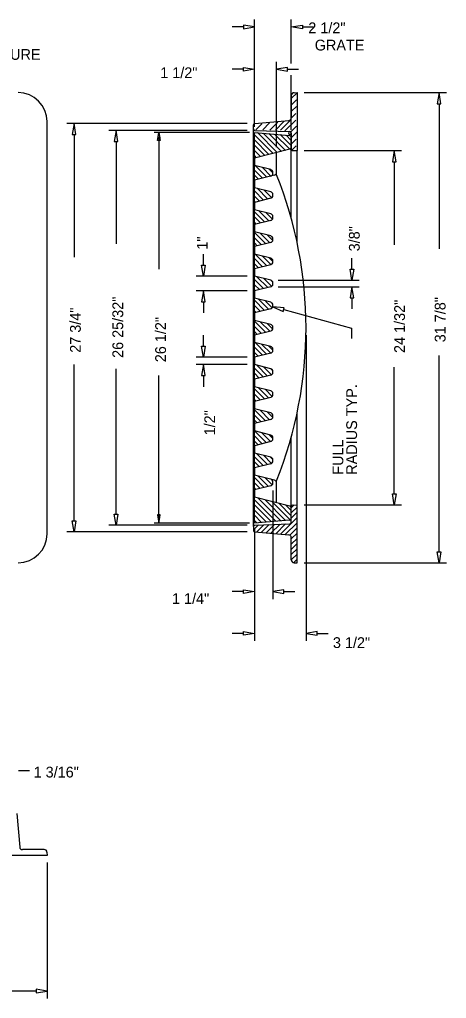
# Model space of a CAD drawing. Extents: x 12.38 to 19.62, y 5.98 to 15.83.
# Drawn here: x 17.01 to 19.38, y 10.38 to 15.83 of the extents above; entities that cross this region are included whole.
import ezdxf

# ---------------------------------------------------------------- set-up
doc = ezdxf.new("R2010")
doc.units = 0
for name, color, linetype in [('Default', 7, 'Continuous'), ('DIMS', 7, 'Continuous'), ('FRAME', 7, 'Continuous'), ('HATCH', 7, 'Continuous'), ('TOP', 7, 'Continuous'), ('V7_LEVEL_12', 7, 'Continuous')]:
    doc.layers.add(name, color=color, linetype=linetype)

# ---------------------------------------------------------------- blocks, each defined once
blk = doc.blocks.new('_X18')
at = {"layer": 'Default'}
for p, q in [((224.48, 235.08), (225.53, 236.13)), ((225.18, 232.25), (229.06, 236.13)), ((225.89, 229.43), (232.6, 236.13)), ((226.6, 226.6), (233.57, 233.57)), ((227.6, 224.07), (232.4, 228.86))]:
    blk.add_line(p, q, dxfattribs=at)
blk = doc.blocks.new('_X19')
at = {"layer": 'Default'}
for p, q in [((239.3, 235.77), (239.67, 236.13)), ((240.01, 232.94), (243.2, 236.13)), ((240.72, 230.11), (246.74, 236.13)), ((241.43, 227.28), (248.86, 234.72)), ((242.2, 224.53), (247.68, 230)), ((244.86, 223.65), (246.5, 225.29))]:
    blk.add_line(p, q, dxfattribs=at)
blk = doc.blocks.new('_X20')
at = {"layer": 'Default'}
for p, q in [((254.84, 233.63), (257.35, 236.13)), ((255.55, 230.8), (260.88, 236.13)), ((256.25, 227.97), (264.15, 235.86)), ((256.96, 225.14), (262.97, 231.15)), ((258.99, 223.63), (261.79, 226.43))]:
    blk.add_line(p, q, dxfattribs=at)
blk = doc.blocks.new('_X21')
at = {"layer": 'Default'}
for p, q in [((269.67, 234.31), (271.49, 236.13)), ((270.38, 231.48), (275.02, 236.13)), ((271.08, 228.66), (278.56, 236.13)), ((271.79, 225.83), (278.25, 232.29)), ((273.22, 223.72), (277.07, 227.58))]:
    blk.add_line(p, q, dxfattribs=at)
blk = doc.blocks.new('_X22')
at = {"layer": 'Default'}
for p, q in [((284.5, 235), (285.63, 236.13)), ((285.2, 232.17), (289.16, 236.13)), ((285.91, 229.34), (292.7, 236.13)), ((286.62, 226.51), (293.54, 233.43)), ((287.66, 224.02), (292.36, 228.72))]:
    blk.add_line(p, q, dxfattribs=at)
blk = doc.blocks.new('_X23')
at = {"layer": 'Default'}
for p, q in [((299.32, 235.69), (299.77, 236.13)), ((300.03, 232.86), (303.31, 236.13)), ((300.74, 230.03), (306.84, 236.13)), ((301.45, 227.2), (308.82, 234.58)), ((302.24, 224.46), (307.65, 229.86)), ((304.98, 223.67), (306.47, 225.15))]:
    blk.add_line(p, q, dxfattribs=at)
blk = doc.blocks.new('_X24')
at = {"layer": 'Default'}
for p, q in [((314.86, 233.54), (317.45, 236.13)), ((315.57, 230.71), (320.98, 236.13)), ((316.27, 227.89), (324.11, 235.72)), ((316.98, 225.06), (322.93, 231.01)), ((319.09, 223.63), (321.75, 226.29))]:
    blk.add_line(p, q, dxfattribs=at)
blk = doc.blocks.new('_X25')
at = {"layer": 'Default'}
for p, q in [((329.69, 234.23), (331.59, 236.13)), ((330.4, 231.4), (335.13, 236.13)), ((331.1, 228.57), (338.66, 236.13)), ((331.81, 225.74), (338.22, 232.15)), ((333.3, 223.7), (337.04, 227.44))]:
    blk.add_line(p, q, dxfattribs=at)
blk = doc.blocks.new('_X26')
at = {"layer": 'Default'}
for p, q in [((344.52, 234.92), (345.73, 236.13)), ((345.22, 232.09), (349.27, 236.13)), ((345.93, 229.26), (352.8, 236.13)), ((346.64, 226.43), (353.5, 233.3)), ((347.72, 223.98), (352.33, 228.58))]:
    blk.add_line(p, q, dxfattribs=at)
blk = doc.blocks.new('_X27')
at = {"layer": 'Default'}
for p, q in [((359.35, 235.6), (359.88, 236.13)), ((360.05, 232.77), (363.41, 236.13)), ((360.76, 229.95), (366.95, 236.13)), ((361.47, 227.12), (368.79, 234.44)), ((362.29, 224.4), (367.61, 229.73)), ((365.12, 223.7), (366.43, 225.01))]:
    blk.add_line(p, q, dxfattribs=at)
blk = doc.blocks.new('_X28')
at = {"layer": 'Default'}
for p, q in [((374.88, 233.46), (377.55, 236.13)), ((375.59, 230.63), (381.09, 236.13)), ((376.3, 227.8), (384.08, 235.58)), ((377, 224.98), (382.9, 230.87)), ((379.2, 223.63), (381.72, 226.16))]:
    blk.add_line(p, q, dxfattribs=at)
blk = doc.blocks.new('_X29')
at = {"layer": 'Default'}
for p, q in [((389.71, 234.15), (391.7, 236.13)), ((390.42, 231.32), (395.23, 236.13)), ((391.12, 228.49), (398.77, 236.13)), ((391.83, 225.66), (398.18, 232.01)), ((393.38, 223.68), (397.01, 227.3))]:
    blk.add_line(p, q, dxfattribs=at)
blk = doc.blocks.new('_X30')
at = {"layer": 'Default'}
for p, q in [((404.54, 234.83), (405.84, 236.13)), ((405.25, 232), (409.37, 236.13)), ((405.95, 229.18), (412.91, 236.13)), ((406.66, 226.35), (413.47, 233.16)), ((407.78, 223.93), (412.29, 228.44))]:
    blk.add_line(p, q, dxfattribs=at)
blk = doc.blocks.new('_X31')
at = {"layer": 'Default'}
for p, q in [((419.37, 235.52), (419.98, 236.13)), ((420.07, 232.69), (423.52, 236.13)), ((420.78, 229.86), (427.05, 236.13)), ((421.49, 227.03), (428.76, 234.3)), ((422.33, 224.34), (427.58, 229.59)), ((425.27, 223.75), (426.38, 224.86))]:
    blk.add_line(p, q, dxfattribs=at)
blk = doc.blocks.new('_X32')
at = {"layer": 'Default'}
for p, q in [((434.9, 233.38), (437.66, 236.13)), ((435.61, 230.55), (441.19, 236.13)), ((436.32, 227.72), (444.04, 235.45)), ((437.03, 224.9), (442.86, 230.73)), ((439.3, 223.63), (441.68, 226.02))]:
    blk.add_line(p, q, dxfattribs=at)
blk = doc.blocks.new('_X38')
at = {"layer": 'Default'}
for p, q in [((865.44, 393.21), (850.84, 407.81)), ((868.69, 393.49), (853.39, 408.8)), ((871.94, 393.78), (858.1, 407.62)), ((875.12, 394.13), (862.82, 406.44)), ((875.84, 396.95), (867.53, 405.26)), ((862.19, 392.92), (850.84, 404.27)), ((858.94, 392.64), (850.84, 400.73)), ((875.84, 400.48), (872.25, 404.08)), ((855.69, 392.36), (850.84, 397.2)), ((852.44, 392.07), (850.84, 393.66))]:
    blk.add_line(p, q, dxfattribs=at)
blk = doc.blocks.new('_X49')
at = {"layer": 'Default'}
for p, q in [((772.6, 411.98), (774.45, 413.83)), ((772.6, 408.44), (776.54, 412.38)), ((765.29, 394.06), (776.54, 405.31)), ((772.6, 404.9), (776.54, 408.84)), ((747.01, 396.99), (750.31, 400.29)), ((749.03, 395.48), (753.97, 400.42)), ((752.29, 395.2), (757.64, 400.55)), ((755.54, 394.91), (761.3, 400.68)), ((758.79, 394.63), (764.96, 400.8)), ((762.04, 394.34), (768.63, 400.93)), ((768.54, 393.77), (776.54, 401.77)), ((771.64, 393.34), (776.54, 398.24)), ((772.6, 390.76), (776.54, 394.7)), ((772.6, 387.23), (776.54, 391.17)), ((772.6, 383.69), (776.54, 387.63)), ((772.6, 380.16), (776.54, 384.1)), ((772.6, 376.62), (776.54, 380.56)), ((774.23, 374.72), (776.54, 377.02))]:
    blk.add_line(p, q, dxfattribs=at)

msp = doc.modelspace()

# ---------------------------------------------------------------- linework, layer by layer
at = {"layer": 'DIMS'}
for p, q in [((18.3147, 15.2408), (18.3147, 15.8273)), ((18.5197, 15.5828), (18.5197, 15.8273)), ((18.2531, 15.7863), (18.1916, 15.7863)), ((18.5812, 15.7863), (18.6427, 15.7863)), ((18.3147, 15.2302), (18.3147, 15.5924)), ((18.4377, 15.1182), (18.4377, 15.5924)), ((18.2531, 15.5514), (18.1916, 15.5514)), ((18.4992, 15.5514), (18.5607, 15.5514)), ((18.5197, 15.2135), (18.5197, 15.5175)), ((18.5918, 15.4209), (19.3826, 15.4209)), ((19.3415, 15.3594), (19.3415, 14.5513)), ((18.2737, 15.2487), (17.2709, 15.2487)), ((18.2737, 15.211), (17.5046, 15.211)), ((18.2873, 15.1998), (17.7564, 15.1998)), ((18.2873, 15.1998), (17.7564, 15.1998)), ((17.3119, 15.1871), (17.3119, 14.5057)), ((17.5456, 15.1495), (17.5456, 14.5793)), ((17.7837, 15.1691), (17.7837, 15.1178)), ((17.7837, 15.1691), (17.7837, 14.4395)), ((18.5918, 15.0981), (19.1336, 15.0981)), ((19.0926, 15.0366), (19.0926, 14.5746)), ((18.0313, 14.4616), (18.0313, 14.5231)), ((18.8568, 14.4389), (18.8568, 14.5004)), ((18.2736, 14.4001), (17.9903, 14.4001)), ((18.4465, 14.3774), (18.8978, 14.3774)), ((18.4465, 14.3408), (18.8978, 14.3408)), ((18.2736, 14.3181), (17.9903, 14.3181)), ((18.8568, 14.2793), (18.8568, 14.2178)), ((18.0313, 14.2566), (18.0313, 14.1951)), ((18.4774, 14.2138), (18.8553, 14.1108)), ((18.8553, 14.1108), (18.8553, 14.054)), ((18.0313, 14.0105), (18.0313, 14.072)), ((18.6017, 14.072), (18.6017, 12.3719)), ((18.2736, 13.949), (17.9903, 13.949)), ((19.3415, 12.8667), (19.3415, 13.9585)), ((17.3119, 13.0396), (17.3119, 13.9082)), ((18.2736, 13.908), (17.9903, 13.908)), ((19.0926, 13.1895), (19.0926, 13.893)), ((17.5456, 13.0766), (17.5456, 13.8853)), ((17.7837, 13.057), (17.7837, 13.8471)), ((18.0313, 13.8465), (18.0313, 13.785)), ((18.4172, 13.2074), (18.4172, 12.6039)), ((18.5918, 13.128), (19.1336, 13.128)), ((17.7837, 13.057), (17.7837, 13.0878)), ((18.2737, 13.0151), (17.5046, 13.0151)), ((18.2873, 13.0263), (17.7564, 13.0263)), ((18.2737, 12.9781), (17.2709, 12.9781)), ((18.3147, 12.9935), (18.3147, 12.3719)), ((18.5918, 12.8052), (19.3826, 12.8052)), ((18.2531, 12.6449), (18.1916, 12.6449)), ((18.4787, 12.6449), (18.5402, 12.6449)), ((18.2531, 12.4129), (18.1916, 12.4129)), ((18.6632, 12.4129), (18.7248, 12.4129)), ((17.0017, 11.6493), (17.0632, 11.6493)), ((17.1617, 11.1383), (17.1617, 10.3821)), ((17.1002, 10.4231), (15.3179, 10.4245))]:
    msp.add_line(p, q, dxfattribs=at)
for points in [[(18.2531, 15.7965), (18.2531, 15.776), (18.3147, 15.7863)], [(18.5812, 15.7965), (18.5812, 15.776), (18.5197, 15.7863)], [(18.2531, 15.5411), (18.2531, 15.5616), (18.3147, 15.5514)], [(18.4992, 15.5411), (18.4992, 15.5616), (18.4377, 15.5514)], [(19.3313, 15.3594), (19.3518, 15.3594), (19.3415, 15.4209)], [(17.3017, 15.1871), (17.3222, 15.1871), (17.3119, 15.2487)], [(17.5353, 15.1495), (17.5558, 15.1495), (17.5456, 15.211)], [(17.7913, 15.1537), (17.7759, 15.1537), (17.7836, 15.1998)], [(17.7889, 15.1691), (17.7786, 15.1691), (17.7837, 15.1998)], [(19.0824, 15.0366), (19.1029, 15.0366), (19.0926, 15.0981)], [(18.0211, 14.4616), (18.0416, 14.4616), (18.0313, 14.4001)], [(18.8466, 14.4389), (18.8671, 14.4389), (18.8568, 14.3774)], [(18.8466, 14.2793), (18.8671, 14.2793), (18.8568, 14.3408)], [(18.0211, 14.2566), (18.0416, 14.2566), (18.0313, 14.3181)], [(18.4747, 14.2039), (18.4801, 14.2237), (18.418, 14.23)], [(18.0211, 14.0105), (18.0416, 14.0105), (18.0313, 13.949)], [(18.0211, 13.8465), (18.0416, 13.8465), (18.0313, 13.908)], [(19.0824, 13.1895), (19.1029, 13.1895), (19.0926, 13.128)], [(17.5353, 13.0766), (17.5558, 13.0766), (17.5456, 13.0151)], [(17.7914, 13.0724), (17.776, 13.0724), (17.7837, 13.0263)], [(17.3017, 13.0396), (17.3222, 13.0396), (17.3119, 12.9781)], [(17.7889, 13.057), (17.7786, 13.057), (17.7837, 13.0263)], [(19.3313, 12.8667), (19.3518, 12.8667), (19.3415, 12.8052)], [(18.2531, 12.6346), (18.2531, 12.6552), (18.3147, 12.6449)], [(18.4787, 12.6346), (18.4787, 12.6552), (18.4172, 12.6449)], [(18.2531, 12.4026), (18.2531, 12.4231), (18.3147, 12.4129)], [(18.6632, 12.4026), (18.6632, 12.4231), (18.6017, 12.4129)], [(17.1002, 10.4333), (17.1002, 10.4128), (17.1617, 10.4231)]]:
    msp.add_lwpolyline(points, close=True, dxfattribs=at)
at = {"layer": 'FRAME'}
for p, q in [((18.535, 15.4203), (18.552, 15.4212)), ((18.552, 15.4212), (18.552, 15.0984)), ((18.5197, 15.4045), (18.5197, 15.2811)), ((17.1617, 12.9667), (17.1617, 15.2594)), ((18.3168, 15.2493), (18.5057, 15.2658)), ((18.3098, 15.2187), (18.3098, 15.2413)), ((18.3098, 13.0074), (18.3098, 15.2174)), ((18.3172, 15.211), (18.5123, 15.2042)), ((18.5197, 15.1965), (18.5197, 15.1063)), ((18.5197, 14.7205), (18.5197, 15.1063)), ((18.5259, 15.0998), (18.552, 15.0984)), ((18.552, 14.5877), (18.552, 15.0984)), ((18.552, 13.1276), (18.552, 13.6384)), ((18.5197, 13.1198), (18.5197, 13.5055)), ((18.5259, 13.1263), (18.552, 13.1276)), ((18.552, 12.8049), (18.552, 13.1276)), ((18.5197, 13.0296), (18.5197, 13.1198)), ((18.3172, 13.0151), (18.5123, 13.0219)), ((18.3098, 13.0077), (18.3098, 12.9851)), ((18.3098, 13.0074), (18.3098, 12.9848)), ((18.3168, 12.9774), (18.5057, 12.9609)), ((18.5197, 12.8218), (18.5197, 12.9456)), ((18.5343, 12.8065), (18.552, 12.8055)), ((18.535, 12.8058), (18.552, 12.8049)), ((16.9928, 11.4109), (17.0091, 11.2244)), ((17.1617, 11.178), (16.8389, 11.178)), ((17.1447, 11.2103), (17.0244, 11.2103)), ((17.1608, 11.195), (17.1617, 11.178))]:
    msp.add_line(p, q, dxfattribs=at)
for centre, radius, start, end in [((17.0002, 15.2594), 0.1615, 0, 90), ((18.5359, 15.4042), 0.0161, 93, 180), ((18.5351, 15.4049), 0.0154, 93, 180), ((18.3175, 15.2416), 0.00769, 95, 180), ((18.5043, 15.2811), 0.0154, 275, 360), ((18.3175, 15.2187), 0.00769, 180, 268), ((18.512, 15.1965), 0.00769, 90, 88), ((18.5262, 15.1063), 0.00648, 180, 267), ((18.5262, 13.1198), 0.00648, 93, 180), ((18.3175, 13.0074), 0.00769, 92, 180), ((18.512, 13.0296), 0.00769, 272, 0), ((17.0002, 12.9667), 0.1615, 270, 0), ((18.3175, 12.9851), 0.00769, 180, 265), ((18.5043, 12.9456), 0.0154, 0, 85), ((18.5359, 12.8219), 0.0161, 180, 267), ((18.5351, 12.8218), 0.0154, 180, 267), ((17.0244, 11.2257), 0.0154, 185, 270), ((17.1447, 11.1942), 0.0161, 3, 90)]:
    msp.add_arc(centre, radius, start, end, dxfattribs=at)
at = {"layer": 'HATCH'}
for p, q in [((18.5522, 15.4205), (18.5195, 15.3878)), ((18.4419, 15.0881), (18.3317, 15.1983)), ((18.4651, 15.0939), (18.3635, 15.1955)), ((18.4883, 15.0997), (18.3953, 15.1928)), ((18.4187, 15.0823), (18.3147, 15.1864)), ((18.3955, 15.0765), (18.3147, 15.1574)), ((18.5115, 15.1055), (18.427, 15.19)), ((18.5197, 15.1263), (18.4588, 15.1872)), ((18.5197, 15.1553), (18.4906, 15.1844)), ((18.3723, 15.0707), (18.3147, 15.1284)), ((18.3491, 15.0649), (18.3147, 15.0994)), ((18.3259, 15.0591), (18.3147, 15.0704))]:
    msp.add_line(p, q, dxfattribs=at)
at = {"layer": 'TOP'}
for p, q in [((18.3147, 15.1998), (18.5104, 15.1827)), ((18.3147, 15.0563), (18.3147, 15.1998)), ((18.5197, 15.1156), (18.5197, 15.1725)), ((18.5119, 15.1056), (18.3147, 15.0563)), ((18.4377, 14.9643), (18.4377, 15.087)), ((18.3147, 15.0563), (18.3147, 15.0153)), ((18.3147, 14.9333), (18.3147, 15.0153)), ((18.4055, 14.9926), (18.3147, 15.0153)), ((18.4172, 14.9709), (18.4172, 14.9776)), ((18.426, 14.9611), (18.3147, 14.9333)), ((18.3147, 14.9333), (18.3147, 14.8922)), ((18.3147, 14.8102), (18.3147, 14.8922)), ((18.4055, 14.8695), (18.3147, 14.8922)), ((18.4055, 14.8329), (18.3147, 14.8102)), ((18.4172, 14.8479), (18.4172, 14.8546)), ((18.3147, 14.8102), (18.3147, 14.7692)), ((18.3147, 14.6872), (18.3147, 14.7692)), ((18.4055, 14.7465), (18.3147, 14.7692)), ((18.4055, 14.7099), (18.3147, 14.6872)), ((18.4172, 14.7248), (18.4172, 14.7316)), ((18.3147, 14.6872), (18.3147, 14.6462)), ((18.3147, 14.5642), (18.3147, 14.6462)), ((18.4055, 14.6235), (18.3147, 14.6462)), ((18.4172, 14.6018), (18.4172, 14.6085)), ((18.4055, 14.5869), (18.3147, 14.5642)), ((18.3147, 14.5642), (18.3147, 14.5231)), ((18.3147, 14.4411), (18.3147, 14.5231)), ((18.4055, 14.5004), (18.3147, 14.5231)), ((18.4172, 14.4788), (18.4172, 14.4855)), ((18.4055, 14.4638), (18.3147, 14.4411)), ((18.3147, 14.4411), (18.3147, 14.4001)), ((18.3147, 14.3181), (18.3147, 14.4001)), ((18.4055, 14.3774), (18.3147, 14.4001)), ((18.4055, 14.3408), (18.3147, 14.3181)), ((18.4172, 14.3557), (18.4172, 14.3625)), ((18.3147, 14.3181), (18.3147, 14.2771)), ((18.3147, 14.1951), (18.3147, 14.2771)), ((18.4055, 14.2544), (18.3147, 14.2771)), ((18.4055, 14.2178), (18.3147, 14.1951)), ((18.4172, 14.2327), (18.4172, 14.2394)), ((18.3147, 14.1951), (18.3147, 14.1541)), ((18.3147, 14.072), (18.3147, 14.1541)), ((18.4055, 14.1313), (18.3147, 14.1541)), ((18.4172, 14.1097), (18.4172, 14.1164)), ((18.4055, 14.0948), (18.3147, 14.072)), ((18.3147, 14.072), (18.3147, 14.031)), ((18.3147, 13.949), (18.3147, 14.031)), ((18.4055, 14.0083), (18.3147, 14.031)), ((18.4055, 13.9717), (18.3147, 13.949)), ((18.3147, 13.949), (18.3147, 13.908)), ((18.4172, 13.9866), (18.4172, 13.9934)), ((18.3147, 13.826), (18.3147, 13.908)), ((18.4055, 13.8853), (18.3147, 13.908)), ((18.4055, 13.8487), (18.3147, 13.826)), ((18.4172, 13.8636), (18.4172, 13.8704)), ((18.3147, 13.826), (18.3147, 13.785)), ((18.3147, 13.7029), (18.3147, 13.785)), ((18.4055, 13.7622), (18.3147, 13.785)), ((18.4055, 13.7257), (18.3147, 13.7029)), ((18.4172, 13.7406), (18.4172, 13.7473)), ((18.3147, 13.7029), (18.3147, 13.6619)), ((18.3147, 13.5799), (18.3147, 13.6619)), ((18.4055, 13.6392), (18.3147, 13.6619)), ((18.4172, 13.6175), (18.4172, 13.6243)), ((18.4055, 13.6026), (18.3147, 13.5799)), ((18.3147, 13.5799), (18.3147, 13.5389)), ((18.3147, 13.4569), (18.3147, 13.5389)), ((18.4055, 13.5162), (18.3147, 13.5389)), ((18.4055, 13.4796), (18.3147, 13.4569)), ((18.3147, 13.4569), (18.3147, 13.4159)), ((18.4172, 13.4945), (18.4172, 13.5013)), ((18.3147, 13.3338), (18.3147, 13.4159)), ((18.4055, 13.3931), (18.3147, 13.4159)), ((18.4055, 13.3566), (18.3147, 13.3338)), ((18.4172, 13.3715), (18.4172, 13.3782)), ((18.3147, 13.3338), (18.3147, 13.2928)), ((18.3147, 13.2108), (18.3147, 13.2928)), ((18.426, 13.265), (18.3147, 13.2928)), ((18.4055, 13.2335), (18.3147, 13.2108)), ((18.4172, 13.2485), (18.4172, 13.2552)), ((18.4377, 13.139), (18.4377, 13.2618)), ((18.3147, 13.2108), (18.3147, 13.1698)), ((18.3147, 13.0263), (18.3147, 13.1698)), ((18.5119, 13.1205), (18.3147, 13.1698)), ((18.5197, 13.0536), (18.5197, 13.1105)), ((18.5104, 13.0434), (18.3147, 13.0263))]:
    msp.add_line(p, q, dxfattribs=at)
for centre, radius, start, end in [((18.5095, 15.1725), 0.0103, 0, 85), ((18.5095, 15.1156), 0.0103, 284.0362, 0), ((18.4018, 14.9776), 0.0154, 360, 75.9638), ((18.4223, 14.976), 0.0154, 284.0362, 0), ((18.4018, 14.9709), 0.0154, 284.0362, 0), ((16.3109, 14.113), 2.2908, 338.1854, 21.8146), ((18.4018, 14.8546), 0.0154, 360, 75.9638), ((18.4018, 14.8479), 0.0154, 284.0362, 0), ((18.4018, 14.7316), 0.0154, 360, 75.9638), ((18.4018, 14.7248), 0.0154, 284.0362, 0), ((18.4018, 14.6085), 0.0154, 360, 75.9638), ((18.4018, 14.6018), 0.0154, 284.0362, 0), ((18.4018, 14.4855), 0.0154, 360, 75.9638), ((18.4018, 14.4788), 0.0154, 284.0362, 0), ((18.4018, 14.3625), 0.0154, 360, 75.9638), ((18.4018, 14.3557), 0.0154, 284.0362, 0), ((18.4018, 14.2394), 0.0154, 360, 75.9638), ((18.4018, 14.2327), 0.0154, 284.0362, 0), ((18.4018, 14.1164), 0.0154, 360, 75.9638), ((18.4018, 14.1097), 0.0154, 284.0362, 0), ((18.4018, 13.9934), 0.0154, 360, 75.9638), ((18.4018, 13.9866), 0.0154, 284.0362, 0), ((18.4018, 13.8704), 0.0154, 360, 75.9638), ((18.4018, 13.8636), 0.0154, 284.0362, 0), ((18.4018, 13.7473), 0.0154, 360, 75.9638), ((18.4018, 13.7406), 0.0154, 284.0362, 0), ((18.4018, 13.6243), 0.0154, 360, 75.9638), ((18.4018, 13.6175), 0.0154, 284.0362, 0), ((18.4018, 13.5013), 0.0154, 360, 75.9638), ((18.4018, 13.4945), 0.0154, 284.0362, 0), ((18.4018, 13.3782), 0.0154, 360, 75.9638), ((18.4018, 13.3715), 0.0154, 284.0362, 0), ((18.4018, 13.2552), 0.0154, 360, 75.9638), ((18.4018, 13.2485), 0.0154, 284.0362, 0), ((18.4223, 13.2501), 0.0154, 360, 75.9638), ((18.5095, 13.1105), 0.0103, 0, 75.9638), ((18.5095, 13.0536), 0.0103, 275, 0)]:
    msp.add_arc(centre, radius, start, end, dxfattribs=at)
at = {"layer": 'V7_LEVEL_12'}
for p, q in [((18.5496, 15.3816), (18.5208, 15.3528)), ((18.5447, 15.3042), (18.5211, 15.2807)), ((18.5479, 15.3437), (18.5213, 15.3171)), ((18.3554, 15.2473), (18.3227, 15.2146)), ((18.399, 15.2528), (18.3607, 15.2145)), ((18.444, 15.2558), (18.4009, 15.2127)), ((18.4792, 15.2596), (18.4312, 15.2116)), ((18.5132, 15.2652), (18.4597, 15.2117)), ((18.5443, 15.2676), (18.4843, 15.2076)), ((18.548, 15.2351), (18.5183, 15.2054)), ((18.5501, 15.2009), (18.5202, 15.171)), ((18.5473, 15.1618), (18.5207, 15.1353)), ((18.5471, 15.1254), (18.5231, 15.1015))]:
    msp.add_line(p, q, dxfattribs=at)

# ---------------------------------------------------------------- block references
at = {"layer": 'HATCH', "xscale": 0.008202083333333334, "yscale": 0.008202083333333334, "rotation": 90}
for name in ['_X32', '_X31', '_X30', '_X29', '_X28', '_X27', '_X26', '_X25', '_X24', '_X23', '_X22', '_X21', '_X20', '_X19', '_X18']:
    msp.add_blockref(name, (20.2514, 11.3718), dxfattribs=at)
at = {"layer": 'HATCH', "xscale": 0.008202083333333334, "yscale": 0.008202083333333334}
for name, p in [('_X49', (12.1828, 9.7328)), ('_X38', (11.336, 9.8116))]:
    msp.add_blockref(name, p, dxfattribs=at)

# ---------------------------------------------------------------- texts
at = {"layer": 'DIMS'}
msp.add_text('1"', height=0.06, rotation=90, dxfattribs=at).set_placement((18.0545, 14.5476))
at = {"layer": 'V7_LEVEL_12'}
for s, p in [(' 2 1/2"', (18.5921, 15.7513)), ('GRATE', (18.6502, 15.6553)), ('PERMAGRIP TEXTURE', (16.2472, 15.6034)), ('1 1/2"', (17.7907, 15.5015)), ('1 1/4"', (17.8564, 12.5764)), ('3 1/2"', (18.7513, 12.3314)), ('1 3/16"', (17.0866, 11.611))]:
    msp.add_text(s, height=0.06, dxfattribs=at).set_placement(p)
for s, p in [('3/8"', (18.9004, 14.5379)), ('26 25/32"', (17.5849, 13.9451)), ('31 7/8"', (19.3777, 14.032)), ('27 3/4"', (17.349, 13.9737)), ('24 1/32"', (19.1521, 13.9726)), ('26 1/2"', (17.8229, 13.9211)), ('RADIUS TYP.', (18.8855, 13.2953)), ('1/2"', (18.0962, 13.5142)), ('FULL ', (18.8092, 13.2953))]:
    msp.add_text(s, height=0.06, rotation=90, dxfattribs=at).set_placement(p)

doc.saveas('drawing.dxf')
